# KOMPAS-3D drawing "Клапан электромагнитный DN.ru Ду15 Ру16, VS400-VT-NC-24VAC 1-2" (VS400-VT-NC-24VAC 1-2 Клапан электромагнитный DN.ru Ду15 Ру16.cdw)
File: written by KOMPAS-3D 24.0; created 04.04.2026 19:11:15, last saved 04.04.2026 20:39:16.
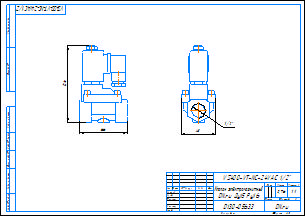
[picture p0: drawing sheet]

Document properties: c3d_UniqueCompID: ef56311e-7521-43dc-8291-0e6108b3d81d; Обозначение: VS400-ET-NC-220VAC 1-2; Наименование: Клапан электромагнитный DN.ru Ду15 Ру16; Автор: artio; Класс точности: c; Знак неуказанной шероховатости: Шероховатость не задана; Рассекать на разрезах: Да; c3d_UniqueCompID: ef56311e-7521-43dc-8291-0e6108b3d81d; Обозначение: VS400-ET-NC-220VAC 3-8; Наименование: Клапан электромагнитный DN.ru Ду10 Ру16; Автор: artio; Класс точности: c; Знак неуказанной шероховатости: Шероховатость не задана; Рассекать на разрезах: Да; Автор: artio; Форматы листов документа: A3; Полное имя файла: VS400-VT-NC-24VAC 1-2 Клапан электромагнитный DN.ru Ду15 Ру16.m3d; Масса: 0.759; Наименование: Клапан электромагнитный DN.ru Ду15 Ру16; Количество листов документа: 1; Примечание: D130-05633

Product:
- Body: Тело 1  | qty 1
    Масса: 1.030062
- Part/product: Клапан электромагнитный DN.ru Ду15 Ру16  | designation VS400-VT-NC-24VAC 1-2
    Масса: 0.759
    Раздел спецификации: Прочие изделия
    Примечание: D130-05633
    additional columns: ef56311e-7521-43dc-8291-0e6108b3d81d; VS400-ET-NC-220VAC 1-2; artio; c; Шероховатость не задана; Да

Views: Вид 1, Спереди, Проекционный вид 2
Referenced files in C:\Users\artio\OneDrive\Рабочий стол\Клапан электромагнитный DN.ru\VS400-ET-NC\VS400-ET-NC-24VDC\: VS400-ET-NC-24VDC 3-8 Клапан электромагнитный DN.ru Ду10 Ру16.m3d
Referenced files in C:\Users\artio\OneDrive\Рабочий стол\Клапан электромагнитный DN.ru\VS400-VT-NC\VS400-VT-NC-24VAC\: VS400-VT-NC-24VAC 1-2 Клапан электромагнитный DN.ru Ду15 Ру16.m3d
Referenced files in C:\Users\artio\OneDrive\Рабочий стол\Клапан электромагнитный DN.ru\VS400-ET-NC\: VS400-ET-NC-24VDC 3-8 Клапан электромагнитный DN.ru Ду10 Ру16.cdw
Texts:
  VS400-VT-NC-24VAC 1-2
  Клапан электромагнитный
  DN.ru Ду15 Ру16
  VS400-VT-NC-24VAC 1/2"
  VS400-VT-NC-24VAC 1/2"-
  Клапан электромагнитный DN.ru Ду15 Ру16
  VS400-VT-NC-24VAC 1-2 Клапан электромагнитный DN.ru Ду15 Ру16
Dimensions and other numbers on the sheet: 0; 3; 2; 4; 48; 1/2"; 66; 106; 1:1; 1; 0,76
